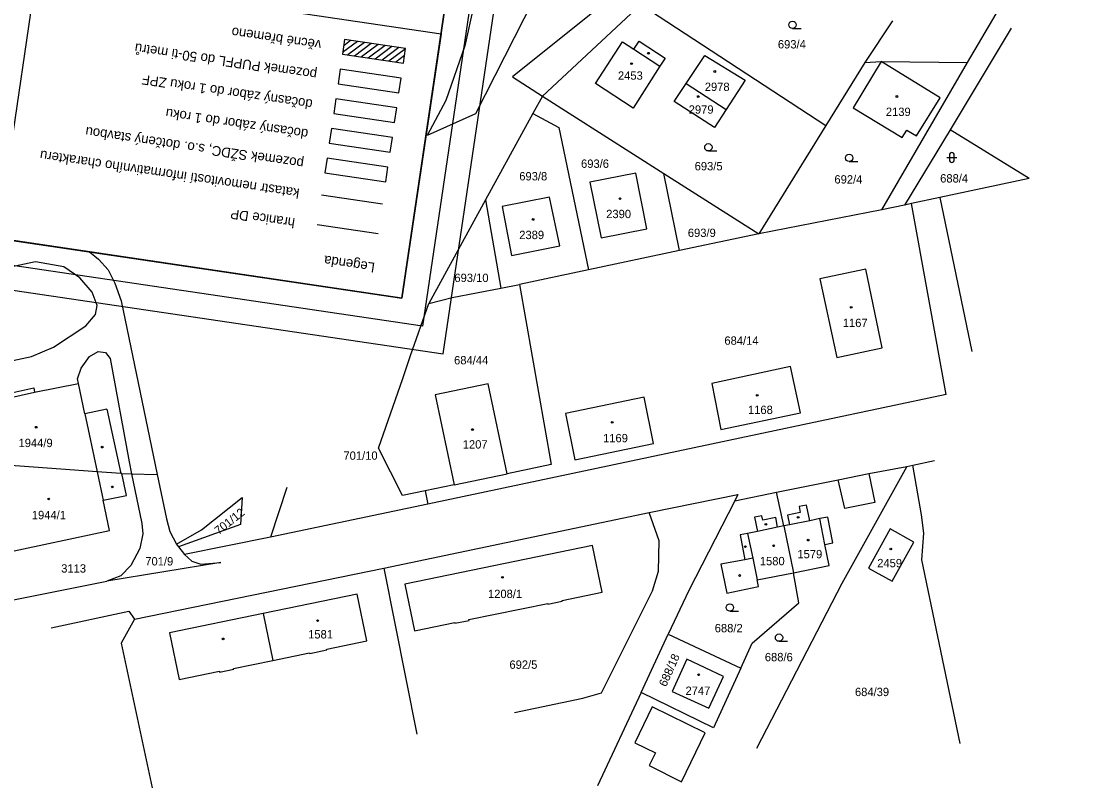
# Model space of a CAD drawing. Extents: x -779330 to -774454, y -1144748 to -1142831.
# Drawn here: x -774928.8 to -774714.8, y -1144748.2 to -1144592 of the extents above; entities that cross this region are included whole.
import ezdxf

# ---------------------------------------------------------------- set-up
doc = ezdxf.new("R2010")
doc.units = 0
for name, color, linetype in [('Hranice parcel', 7, 'Continuous'), ('legenda - Vrstva 7', 7, 'Continuous'), ('Parcelní čísla', 7, 'Continuous'), ('PUPFL - do 50 m', 7, 'Continuous'), ('VBř', 7, 'Continuous'), ('Vnitřní kresba', 7, 'Continuous'), ('Vrstva 1', 7, 'Continuous'), ('Vrstva 3', 7, 'Continuous'), ('Značky budov', 7, 'Continuous'), ('Značky kultur', 7, 'Continuous')]:
    doc.layers.add(name, color=color, linetype=linetype)

msp = doc.modelspace()

# ---------------------------------------------------------------- linework, layer by layer
at = {"layer": 'Hranice parcel'}
for p, q in [((-774802.54, -1144588.71), (-774822.59, -1144607.36)), ((-774802.54, -1144588.71), (-774764.91, -1144613.3)), ((-774751.3, -1144592.01), (-774756.92, -1144600.48)), ((-774727.11, -1144593.47), (-774739.59, -1144614.19)), ((-774756.92, -1144600.48), (-774764.91, -1144613.3)), ((-774753.47, -1144630.52), (-774736.03, -1144600.5)), ((-774828.68, -1144603.4), (-774822.59, -1144607.36)), ((-774793.3, -1144604.79), (-774785.17, -1144610.03)), ((-774822.59, -1144607.36), (-774824.51, -1144610.86)), ((-774822.59, -1144607.36), (-774797.88, -1144623.07)), ((-774824.51, -1144610.86), (-774834.17, -1144628.45)), ((-774764.91, -1144613.3), (-774778.49, -1144635.4)), ((-774739.59, -1144614.19), (-774748.83, -1144629.53)), ((-774723.46, -1144624.12), (-774739.59, -1144614.19)), ((-774797.88, -1144623.07), (-774778.49, -1144635.4)), ((-774794.67, -1144638.8), (-774797.88, -1144623.07)), ((-774855.14, -1144629.35), (-774867.55, -1144627.51)), ((-774834.17, -1144628.45), (-774845.74, -1144649.55)), ((-774834.17, -1144628.45), (-774831.04, -1144646.46)), ((-774753.47, -1144630.52), (-774778.49, -1144635.4)), ((-774748.83, -1144629.53), (-774753.47, -1144630.52)), ((-774778.49, -1144635.4), (-774794.67, -1144638.8)), ((-774794.67, -1144638.8), (-774813.19, -1144642.7)), ((-774813.19, -1144642.7), (-774827.26, -1144645.66)), ((-774831.04, -1144646.46), (-774827.26, -1144645.66)), ((-774906.75, -1144681.8), (-774906.25, -1144684.23)), ((-774748.4, -1144682.72), (-774747.18, -1144682.46)), ((-774747.18, -1144682.46), (-774742.75, -1144681.54)), ((-774908.19, -1144684.17), (-774908.46, -1144684.16)), ((-774907.24, -1144688.69), (-774908.19, -1144684.17)), ((-774908.19, -1144684.17), (-774906.25, -1144684.23)), ((-774906.25, -1144684.23), (-774904.18, -1144694.39)), ((-774906.25, -1144684.23), (-774901, -1144684.4)), ((-774840.57, -1144686.5), (-774829.78, -1144684.25)), ((-774840.57, -1144686.5), (-774846.49, -1144687.73)), ((-774874.66, -1144687.05), (-774877.94, -1144697.17)), ((-774846.49, -1144687.73), (-774845.95, -1144690.45)), ((-774783.44, -1144689.71), (-774774.93, -1144688)), ((-774773.41, -1144694.86), (-774774.93, -1144688)), ((-774845.95, -1144690.45), (-774877.94, -1144697.17)), ((-774854.89, -1144703.44), (-774800.85, -1144692.1)), ((-774773.41, -1144694.86), (-774771.49, -1144704.37)), ((-774877.94, -1144697.17), (-774895.46, -1144700.66)), ((-774896.67, -1144699.12), (-774895.46, -1144700.66)), ((-774905.67, -1144713.84), (-774854.89, -1144703.44)), ((-774854.89, -1144703.44), (-774848.19, -1144737.24)), ((-774932.31, -1144710.34), (-774911.3, -1144706.11)), ((-774837.54, -1144713.93), (-774821.5, -1144710.63)), ((-774879.42, -1144712.65), (-774877.45, -1144722.22)), ((-774802.48, -1144728.76), (-774796.96, -1144716.92)), ((-774796.96, -1144716.92), (-774782.18, -1144723.82)), ((-774782.18, -1144723.82), (-774787.72, -1144735.97)), ((-774802.48, -1144728.76), (-774811.36, -1144747.79)), ((-774787.72, -1144735.97), (-774802.48, -1144728.76))]:
    msp.add_line(p, q, dxfattribs=at)
for points in [[(-774875.06, -1144456.94), (-774861.71, -1144492.14), (-774848.12, -1144528.64), (-774837.33, -1144580.31), (-774836.58, -1144588.82), (-774838.41, -1144597.12), (-774842.25, -1144608.21), (-774846.04, -1144615.37)], [(-774748.16, -1144529.45), (-774767.69, -1144549.86), (-774786.26, -1144569.27), (-774806.89, -1144585.87), (-774828.68, -1144603.4)], [(-774736.03, -1144600.5), (-774724.37, -1144580.58), (-774714.76, -1144564.69)], [(-774822.46, -1144583.82), (-774836.2, -1144610.91), (-774846.04, -1144615.37)], [(-774803.94, -1144597.81), (-774802.87, -1144596.17), (-774797.57, -1144599.61), (-774798.65, -1144601.26), (-774804.08, -1144609.78), (-774811.78, -1144604.76), (-774806.26, -1144596.27), (-774803.94, -1144597.81)], [(-774793.3, -1144604.79), (-774789.49, -1144599.05), (-774781.32, -1144604.06), (-774785.17, -1144610.03)], [(-774748.37, -1144614.25), (-774746.39, -1144615.4), (-774741.57, -1144607.66), (-774753.64, -1144600.28), (-774759.32, -1144609.74), (-774749.33, -1144615.74), (-774748.37, -1144614.25)], [(-774756.92, -1144600.48), (-774753.64, -1144600.28), (-774736.03, -1144600.5)], [(-774785.17, -1144610.03), (-774787.58, -1144613.73), (-774795.73, -1144608.42), (-774793.3, -1144604.79)], [(-774824.51, -1144610.86), (-774819.26, -1144613.74), (-774813.19, -1144642.7)], [(-774812.92, -1144624.89), (-774810.62, -1144636.2), (-774801.33, -1144634.35), (-774803.54, -1144623.02), (-774812.92, -1144624.89)], [(-774723.46, -1144624.12), (-774741.65, -1144628), (-774747.42, -1144629.23), (-774748.83, -1144629.53)], [(-774819.07, -1144637.82), (-774821.12, -1144627.9), (-774830.77, -1144629.8), (-774828.85, -1144639.76), (-774819.07, -1144637.82)], [(-774914.8, -1144639.06), (-774912.97, -1144640.51), (-774911.03, -1144642.74), (-774909.67, -1144645.42), (-774908.35, -1144649.03), (-774901, -1144684.4)], [(-774945.87, -1144666.63), (-774946.32, -1144664.58), (-774926.62, -1144660.38), (-774922.11, -1144658.43), (-774915.55, -1144654.1), (-774913.6, -1144651.77), (-774913.25, -1144649.95), (-774914.27, -1144647.26), (-774916.78, -1144644.31), (-774920.05, -1144642.11), (-774925.78, -1144641.08), (-774958.14, -1144647.94), (-774959.58, -1144649.16), (-774960.39, -1144650.94), (-774960.12, -1144654.79), (-775016.68, -1144666.62), (-775017.69, -1144663.53), (-775019.98, -1144661.57), (-775022.9, -1144661.4), (-775041.66, -1144665.85), (-775042.33, -1144666.27)], [(-774766.09, -1144644.56), (-774762.67, -1144660.59), (-774753.39, -1144658.62), (-774756.74, -1144642.56), (-774766.09, -1144644.56)], [(-774827.26, -1144645.66), (-774820.78, -1144682.35), (-774829.78, -1144684.25)], [(-774845.74, -1144649.55), (-774840.94, -1144648.33), (-774831.04, -1144646.46)], [(-774846.49, -1144687.73), (-774851.07, -1144688.67), (-774855.98, -1144679.04), (-774851.04, -1144664.83), (-774849.42, -1144660.15), (-774845.74, -1144649.55)], [(-774939.02, -1144670.52), (-774935.21, -1144669.68), (-774935.4, -1144668.8), (-774926.17, -1144666.76), (-774925.98, -1144667.64), (-774917.05, -1144665.85), (-774917.24, -1144664.89), (-774916.52, -1144662.76), (-774914.78, -1144660.38), (-774913.04, -1144659.34), (-774911.57, -1144659.55), (-774910.63, -1144660.73), (-774906.75, -1144681.8)], [(-774770.06, -1144671.81), (-774772.04, -1144662.4), (-774788.1, -1144665.87), (-774786.25, -1144675.22), (-774770.06, -1144671.81)], [(-774829.78, -1144684.25), (-774833.61, -1144665.89), (-774844.4, -1144668.13), (-774840.57, -1144686.5)], [(-774740.35, -1144668.12), (-774804.51, -1144681.69), (-774845.95, -1144690.45)], [(-774817.9, -1144671.95), (-774816, -1144681.38), (-774799.94, -1144678.05), (-774801.87, -1144668.66), (-774817.9, -1144671.95)], [(-774908.46, -1144684.16), (-774913.27, -1144683.81), (-774936.49, -1144682.12)], [(-774737.54, -1144739.16), (-774745.35, -1144701.76), (-774744.94, -1144696.32), (-774745.37, -1144692.59), (-774747.18, -1144682.46)], [(-774901, -1144684.4), (-774899.13, -1144693.4), (-774898.48, -1144696.02), (-774897.08, -1144698.55)], [(-774748.4, -1144682.72), (-774761.63, -1144706.59), (-774778.98, -1144740.2)], [(-774774.93, -1144688), (-774762.35, -1144685.44), (-774756.14, -1144684.16), (-774748.4, -1144682.72)], [(-774932.38, -1144700.37), (-774910.73, -1144695.8), (-774912.04, -1144689.58), (-774907.24, -1144688.69)], [(-774800.85, -1144692.1), (-774782.79, -1144688.44), (-774783.44, -1144689.71)], [(-774897.08, -1144698.55), (-774891.98, -1144695.66), (-774883.69, -1144689.03)], [(-774883.69, -1144689.03), (-774884.07, -1144694.58), (-774896.67, -1144699.12)], [(-774783.44, -1144689.71), (-774792.8, -1144707.99), (-774796.96, -1144716.92)], [(-774771.49, -1144704.37), (-774764.19, -1144702.91), (-774765.05, -1144698.61), (-774763.44, -1144698.29), (-774764.49, -1144693.04), (-774766.09, -1144693.37), (-774768.17, -1144693.79), (-774768.82, -1144690.6), (-774770.34, -1144690.93), (-774770.1, -1144692.15), (-774772.68, -1144692.65), (-774772.28, -1144694.62), (-774773.41, -1144694.86)], [(-774828.24, -1144732.83), (-774814.33, -1144729.9), (-774810.58, -1144728.84), (-774800.16, -1144708.09), (-774798.93, -1144704.09), (-774798.79, -1144697.9), (-774800.85, -1144692.1)], [(-774773.41, -1144694.86), (-774774.69, -1144695.13), (-774775.09, -1144693.13), (-774777.7, -1144693.67), (-774777.89, -1144692.8), (-774779.39, -1144693.1), (-774778.81, -1144695.96), (-774780.83, -1144696.41), (-774782.35, -1144696.68), (-774781.34, -1144701.74), (-774786.23, -1144702.67), (-774785.07, -1144708.51), (-774778.58, -1144707.2), (-774778.86, -1144705.86), (-774771.49, -1144704.37)], [(-774904.18, -1144694.39), (-774903.92, -1144696.48), (-774904.55, -1144699.44), (-774906.36, -1144702.9), (-774908.45, -1144705.04), (-774911.3, -1144706.11)], [(-774756.18, -1144703.43), (-774751.35, -1144706.09), (-774746.93, -1144698.13), (-774751.77, -1144695.43), (-774756.18, -1144703.43)], [(-774897.08, -1144698.55), (-774896.97, -1144698.74), (-774896.67, -1144699.12)], [(-774821.5, -1144710.63), (-774821.47, -1144710.77), (-774818.55, -1144710.18), (-774818.58, -1144710.06), (-774810.44, -1144708.36), (-774812.39, -1144698.85), (-774850.61, -1144706.72), (-774848.62, -1144716.23), (-774840.43, -1144714.53), (-774840.4, -1144714.68), (-774837.51, -1144714.08), (-774837.54, -1144713.93)], [(-774895.46, -1144700.66), (-774894, -1144702.04), (-774892.13, -1144702.65), (-774888.07, -1144702.3), (-774911.3, -1144706.11)], [(-774782.18, -1144723.82), (-774779.87, -1144718.74), (-774770.39, -1144710.52), (-774771.49, -1144704.37)], [(-774877.45, -1144722.22), (-774870.01, -1144720.67), (-774869.97, -1144720.82), (-774866.48, -1144720.1), (-774866.5, -1144719.95), (-774858.34, -1144718.28), (-774860.3, -1144708.72), (-774879.42, -1144712.65)], [(-774922.59, -1144715.6), (-774906.77, -1144712.23), (-774905.67, -1144713.84)], [(-774905.67, -1144713.84), (-774908.39, -1144718.7), (-774902.06, -1144748.21)], [(-774879.42, -1144712.65), (-774898.54, -1144716.59), (-774896.55, -1144726.09), (-774888.36, -1144724.45), (-774888.33, -1144724.6), (-774885.44, -1144724.01), (-774885.47, -1144723.86), (-774877.45, -1144722.22)], [(-774793.15, -1144722.01), (-774796.15, -1144728.54), (-774788.67, -1144731.95), (-774785.72, -1144725.48), (-774793.15, -1144722.01)], [(-774794.25, -1144746.93), (-774789.42, -1144737), (-774800.21, -1144731.7), (-774803.78, -1144739), (-774799.57, -1144741.02), (-774800.88, -1144743.66), (-774794.25, -1144746.93)]]:
    msp.add_lwpolyline(points, dxfattribs=at)
at = {"layer": 'legenda - Vrstva 7'}
msp.add_lwpolyline([(-774851.19, -1144648.48), (-774933.55, -1144636.29), (-774925.58, -1144582.47), (-774843.23, -1144594.66)], close=True, dxfattribs=at)
at = {"layer": 'PUPFL - do 50 m'}
msp.add_lwpolyline([(-774851.35, -1144603.71), (-774863.76, -1144601.87), (-774864.2, -1144604.84), (-774851.79, -1144606.68), (-774851.35, -1144603.71)], dxfattribs=at)
at = {"layer": 'VBř'}
for p, q in [((-774860.23, -1144596.22), (-774863.26, -1144598.47)), ((-774861.63, -1144596.02), (-774863.05, -1144597.07)), ((-774858.83, -1144596.43), (-774862.24, -1144598.96)), ((-774857.43, -1144596.64), (-774860.84, -1144599.17)), ((-774856.03, -1144596.85), (-774859.44, -1144599.37)), ((-774854.63, -1144597.05), (-774858.04, -1144599.58)), ((-774853.23, -1144597.26), (-774856.64, -1144599.79)), ((-774851.83, -1144597.47), (-774855.24, -1144600)), ((-774850.46, -1144597.69), (-774853.84, -1144600.2)), ((-774850.66, -1144599.09), (-774852.44, -1144600.41)), ((-774850.87, -1144600.49), (-774851.04, -1144600.62))]:
    msp.add_line(p, q, dxfattribs=at)
for points in [[(-774850.45, -1144597.67), (-774862.87, -1144595.83), (-774863.3, -1144598.8), (-774850.89, -1144600.64)], [(-774850.89, -1144600.64), (-774850.45, -1144597.67)]]:
    msp.add_lwpolyline(points, dxfattribs=at)
at = {"layer": 'Vnitřní kresba'}
for p, q in [((-774803.94, -1144597.81), (-774798.65, -1144601.26)), ((-774741.65, -1144628), (-774735.16, -1144659.31)), ((-774740.35, -1144668.12), (-774747.42, -1144629.23)), ((-774915.75, -1144672.01), (-774917.05, -1144665.85)), ((-774935.21, -1144669.68), (-774925.98, -1144667.64)), ((-774911.27, -1144671.06), (-774915.75, -1144672.01)), ((-774911.27, -1144671.06), (-774908.46, -1144684.16)), ((-774915.75, -1144672.01), (-774913.27, -1144683.81)), ((-774913.27, -1144683.81), (-774912.99, -1144685.12)), ((-774756.14, -1144684.16), (-774754.91, -1144690.06)), ((-774912.99, -1144685.12), (-774912.23, -1144688.69)), ((-774761.02, -1144691.28), (-774762.35, -1144685.44)), ((-774912.23, -1144688.69), (-774912.04, -1144689.58)), ((-774754.91, -1144690.06), (-774761.02, -1144691.28)), ((-774774.69, -1144695.13), (-774778.81, -1144695.96)), ((-774768.17, -1144693.79), (-774772.28, -1144694.62)), ((-774765.05, -1144698.61), (-774766.09, -1144693.37)), ((-774780.83, -1144696.41), (-774779.75, -1144701.45)), ((-774779.75, -1144701.45), (-774781.34, -1144701.74)), ((-774779.75, -1144701.45), (-774778.86, -1144705.86))]:
    msp.add_line(p, q, dxfattribs=at)
at = {"layer": 'Vrstva 1'}
for points in [[(-774799.29, -1144366.04), (-776045.7, -1144181.56), (-776089.18, -1144475.34), (-774842.77, -1144659.83)], [(-774846.98, -1144654.15), (-776083.5, -1144471.13), (-776041.48, -1144187.23), (-774804.97, -1144370.25)], [(-774810.64, -1144374.46), (-775834.48, -1144222.92), (-775875.04, -1144496.94), (-774851.19, -1144648.48)], [(-774851.19, -1144648.48), (-775875.04, -1144496.94), (-775834.48, -1144222.92), (-774810.64, -1144374.46)]]:
    msp.add_lwpolyline(points, close=True, dxfattribs=at)
at = {"layer": 'Vrstva 3'}
msp.add_line((-774856.04, -1144635.39), (-774868.45, -1144633.55), dxfattribs=at)
for points in [[(-774851.35, -1144603.71), (-774863.76, -1144601.87), (-774864.2, -1144604.84), (-774851.79, -1144606.68), (-774851.35, -1144603.71)], [(-774852.24, -1144609.75), (-774864.65, -1144607.91), (-774865.09, -1144610.88), (-774852.68, -1144612.72), (-774852.24, -1144609.75)], [(-774852.24, -1144609.75), (-774864.65, -1144607.91), (-774865.09, -1144610.88), (-774852.68, -1144612.72), (-774852.24, -1144609.75)], [(-774853.14, -1144615.79), (-774865.55, -1144613.95), (-774865.99, -1144616.92), (-774853.57, -1144618.76), (-774853.14, -1144615.79)], [(-774853.14, -1144615.79), (-774865.55, -1144613.95), (-774865.99, -1144616.92), (-774853.57, -1144618.76), (-774853.14, -1144615.79)], [(-774854.03, -1144621.83), (-774866.44, -1144619.99), (-774866.88, -1144622.96), (-774854.47, -1144624.79), (-774854.03, -1144621.83)], [(-774854.03, -1144621.83), (-774866.44, -1144619.99), (-774866.88, -1144622.96), (-774854.47, -1144624.79), (-774854.03, -1144621.83)]]:
    msp.add_lwpolyline(points, dxfattribs=at)
at = {"layer": 'Značky budov'}
for centre in [(-774800.99, -1144598.6), (-774804.44, -1144600.73), (-774787.49, -1144602.32), (-774790.86, -1144607.42), (-774750.41, -1144607.41), (-774806.79, -1144628.22), (-774824.49, -1144632.44), (-774759.7, -1144650.35), (-774778.84, -1144668.27), (-774808.37, -1144673.75), (-774925.66, -1144674.75), (-774836.82, -1144675.23), (-774912.22, -1144678.8), (-774910.16, -1144686.91), (-774923.11, -1144689.36), (-774770.51, -1144693.11), (-774777.09, -1144694.53), (-774768.46, -1144697.74), (-774781.27, -1144699.07), (-774775.49, -1144698.89), (-774751.66, -1144699.55), (-774830.72, -1144705.33), (-774782.43, -1144704.95), (-774868.36, -1144714.14), (-774887.59, -1144717.85), (-774790.77, -1144725.15)]:
    msp.add_circle(centre, 0.175, dxfattribs=at)
at = {"layer": 'Značky kultur'}
for p, q in [((-774771.65, -1144593.58), (-774769.9, -1144593.58)), ((-774788.8, -1144618.51), (-774787.05, -1144618.51)), ((-774740.22, -1144619.83), (-774738.22, -1144619.83)), ((-774739.72, -1144619.33), (-774739.72, -1144620.33)), ((-774738.72, -1144620.33), (-774738.72, -1144619.33)), ((-774760.14, -1144620.67), (-774758.39, -1144620.67)), ((-774784.42, -1144712.21), (-774782.67, -1144712.21)), ((-774774.41, -1144718.35), (-774772.66, -1144718.35))]:
    msp.add_line(p, q, dxfattribs=at)
for centre in [(-774771.65, -1144592.83), (-774788.8, -1144617.76), (-774760.14, -1144619.92), (-774784.42, -1144711.46), (-774774.41, -1144717.6)]:
    msp.add_circle(centre, 0.75, dxfattribs=at)
for centre, start, end in [((-774739.22, -1144619.33), 0, 180), ((-774739.22, -1144620.33), 180, 359.9879)]:
    msp.add_arc(centre, 0.5, start, end, dxfattribs=at)

# ---------------------------------------------------------------- texts
at = {"layer": 'Parcelní čísla'}
for s, p in [('693/4', (-774774.64, -1144597.63)), ('2453', (-774807.21, -1144604)), ('2978', (-774789.53, -1144606.29)), ('2979', (-774792.8, -1144610.92)), ('2139', (-774752.66, -1144611.38)), ('693/6', (-774814.72, -1144621.94)), ('693/5', (-774791.59, -1144622.45)), ('693/8', (-774827.3, -1144624.5)), ('692/4', (-774763.13, -1144625.14)), ('688/4', (-774741.6, -1144624.93)), ('2390', (-774809.6, -1144632.18)), ('2389', (-774827.3, -1144636.45)), ('693/9', (-774792.98, -1144636.02)), ('693/10', (-774840.51, -1144645.19)), ('1167', (-774761.43, -1144654.36)), ('684/14', (-774785.53, -1144657.96)), ('684/44', (-774840.57, -1144661.96)), ('1168', (-774780.73, -1144672.06)), ('1169', (-774810.24, -1144677.82)), ('1944/9', (-774929.26, -1144678.8)), ('1207', (-774838.81, -1144679.1)), ('701/10', (-774863.1, -1144681.38)), ('1944/1', (-774926.55, -1144693.48)), ('701/9', (-774903.45, -1144702.9)), ('1580', (-774778.32, -1144702.86)), ('1579', (-774770.67, -1144701.44)), ('2459', (-774754.42, -1144703.27)), ('3113', (-774920.57, -1144704.36)), ('1208/1', (-774833.67, -1144709.54)), ('1581', (-774870.29, -1144717.77)), ('688/2', (-774787.5, -1144716.51)), ('688/6', (-774777.3, -1144722.41)), ('692/5', (-774829.3, -1144723.94)), ('2747', (-774793.45, -1144729.26)), ('684/39', (-774758.95, -1144729.5))]:
    msp.add_text(s, height=1.7, dxfattribs=at).set_placement(p)
for s, rotation, p in [('701/12', 38, (-774888.52, -1144696.72)), ('688/18', 66, (-774797.4, -1144727.73))]:
    msp.add_text(s, height=1.7, rotation=rotation, dxfattribs=at).set_placement(p)
at = {"layer": 'Vrstva 3'}
for s, p in [('věcné břemeno', (-774867.49, -1144596)), ('pozemek PUPFL do 50-ti metrů', (-774868.39, -1144602.04)), ('dočasný zábor do 1 roku ZPF', (-774869.28, -1144608.08)), ('dočasný zábor do 1 roku', (-774870.18, -1144614.12)), ('pozemek SŽDC, s.o. dotčený stavbou', (-774871.07, -1144620.15)), ('katastr nemovitostí informativního charakteru', (-774871.96, -1144626.19)), ('hranice DP', (-774872.86, -1144632.23)), ('Legenda', (-774856.6, -1144641.31))]:
    msp.add_text(s, height=2, rotation=171.5822, dxfattribs=at).set_placement(p)

doc.saveas('drawing.dxf')
